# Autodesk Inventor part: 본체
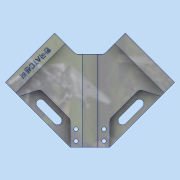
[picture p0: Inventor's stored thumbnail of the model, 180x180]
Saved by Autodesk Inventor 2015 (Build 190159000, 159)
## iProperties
Created: 2019-04
Part Number: 본체
Material: 알루미늄 6061
Document SubType Name: Modeling
Designer: SCD-A02
Density: 2.7 g/cm^3
Appearance: 알루미늄 - 평지
Mass: 601.509 g
Surface Area: 426.536 cm^2
Volume: 222.781 cm^3
Author: SCD-A02
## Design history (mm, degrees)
sketch "스케치1"
  geometry: L1 (-84.853, 0)-(0, 84.853); L2 (0, 84.853)-(84.853, 0); L3 (84.853, 0)-(0, -84.853); L4 (0, -84.853)-(-84.853, 0); L5 (-84.853, 0)-(84.853, 0); L6 (0, 84.853)-(0, -84.853); 1 further point
  constraints: 12 end point, 2 midpoint, 2 parallel, 1 perpendicular
extrude "돌출1" new body sketch "스케치1" distance "d2" = 18; taper "d3" = 0 deg
sketch "스케치2"
  geometry: L1 (0, 84.853)-(-84.853, 0) reference; L2 (-84.853, 0)-(0, -84.853) reference; L3 (0, -84.853)-(84.853, 0) reference; L4 (84.853, 0)-(0, 84.853) reference; L5 (-84.853, 0)-(-50.467, -34.386); L6 (-84.853, 0)-(-49.497, 35.355); L7 (64.853, 0)-(64.853, 20); L8 (64.853, 0)-(64.853, -20); L9 (64.853, -20)-(84.853, 0); L10 (84.853, 0)-(64.853, 20); 1 further point
  constraints: 12 end point, 5 point on line, 1 collinear, 1 vertical
  dimensions: "d6" = 20 distance of L3.end L7.start; "d7" = 20 distance from line of L3.end L8; "d8" = 70 distance from line of L6.end L4; "d9" = 48.62899 distance from line of L5.end L1
extrude "돌출2" cut sketch "스케치2" distance "d10" = 18; taper "d11" = 0 deg
sketch "스케치3"
  geometry: L1 (64.853, -20)-(64.853, 20) reference; L2 (64.853, 20)-(0, 84.853) reference; L3 (0, -84.853)-(64.853, -20) reference; L4 (64.853, 0)-(-28.147, 0); L5 (-84.853, 0)-(-49.497, -35.355); L6 (-84.853, 0)-(-49.497, 35.355); L7 (-49.497, -35.355)-(-28.147, -14.005); L8 (-49.497, 35.355)-(-28.147, 14.005); L9 (-28.147, 0)-(-28.147, 5.408); L10 (-28.147, 5.408)-(-28.147, 14.005); L11 (-28.147, 0)-(-28.147, -14.005); 1 further point
  constraints: 16 end point, 5 parallel, 1 horizontal, 1 midpoint, 1 point on line, 1 vertical
  dimensions: "d12" = 93 distance of L4.start L4.end; "d13" = 50 distance of L5.start L5.end; "d14" = 50 distance of L5.start L6.end; "d15" = 76.07918 distance from line of L9.end L2
extrude "돌출3" cut sketch "스케치3" stored distance "d16" = 0; taper "d17" = 0 deg
sketch "스케치4"
  geometry: L1 (-28.147, 14.005)-(-28.147, -14.005) reference; L2 (64.853, -20)-(64.853, 20) reference; L3 (-28.147, 0)-(64.853, 0); L4 (-28.147, -8)-(64.853, -8); L5 (-28.147, 8)-(64.853, 8); L6 (-28.147, -8)-(-28.147, 8); L7 (64.853, -8)-(64.853, 8); 1 further point
  constraints: 10 end point, 2 midpoint, 2 parallel, 1 collinear, 1 perpendicular, 1 point on line
  dimensions: "d18" = 8 distance between parallel lines of L3 L4; "d19" = 8 distance between parallel lines of L3 L5
extrude "돌출4" cut sketch "스케치4" distance "d20" = 3.5; taper "d21" = 0 deg
sketch "스케치5"
  geometry: L1 (-64.853, 20)-(-64.853, -20) reference; L2 (28.147, -14.005)-(28.147, 14.005) reference; L3 (-64.853, 8)-(-64.853, -8) reference; L4 (28.147, 8)-(-64.853, 8) reference; L5 (28.147, -8)-(28.147, 8) reference; L6 (-64.853, -8)-(28.147, -8) reference; L7 (-64.853, 0)-(28.147, 0); L8 (-64.853, 6)-(28.147, 6); L9 (-64.853, -6)-(28.147, -6); L10 (-64.853, -6)-(-64.853, 6); L11 (28.147, -6)-(28.147, 6); 1 further point
  constraints: 10 end point, 2 collinear, 2 midpoint, 2 parallel
  dimensions: "d22" = 6 distance between parallel lines of L7 L8; "d23" = 6 distance between parallel lines of L7 L9
extrude "돌출5" cut sketch "스케치5" distance "d24" = 3; taper "d25" = 0 deg
sketch "스케치6"
  geometry: L1 (-49.497, -35.355)-(0, -84.853) reference; L2 (0, -84.853)-(64.853, -20) reference; L3 (-28.147, -14.005)-(-28.147, -8) reference; L4 (-28.147, -8)-(64.853, -8) reference; L5 (64.853, -8)-(64.853, -20) reference; L6 (64.853, -20)-(0, -84.853) reference; L7 (0, -84.853)-(-49.497, -35.355) reference; L8 (-49.497, -35.355)-(-28.147, -14.005) reference; L9 (-28.147, 8)-(-28.147, 14.005) reference; L10 (-28.147, 14.005)-(-49.497, 35.355) reference; L11 (-49.497, 35.355)-(0, 84.853) reference; L12 (0, 84.853)-(64.853, 20) reference; L13 (64.853, 20)-(64.853, 8) reference; L14 (64.853, 8)-(-28.147, 8) reference; L15 (-38.891, -24.749)-(10.607, -74.246); L16 (0, -84.853)-(10.607, -74.246); L17 (-49.497, -35.355)-(-38.891, -24.749); 1 further point
  constraints: 6 end point, 2 collinear, 1 parallel
  dimensions: "d26" = 15 distance between parallel lines of L1 L15
extrude "돌출6" join sketch "스케치6" distance "d27" = 24; taper "d28" = 0 deg
sketch "스케치7"
  geometry: L1 (0, 84.853)-(-49.497, 35.355) reference; L2 (-28.147, -14.005)-(-28.147, -8) reference; L3 (-28.147, -8)-(64.853, -8) reference; L4 (64.853, -8)-(64.853, -20) reference; L5 (64.853, -20)-(10.607, -74.246) reference; L6 (-38.891, -24.749)-(10.607, -74.246) reference; L7 (-49.497, -35.355)-(-38.891, -24.749) reference; L8 (0, -84.853)-(-49.497, -35.355) reference; L9 (10.607, -74.246)-(0, -84.853) reference; L10 (-38.891, -24.749)-(-28.147, -14.005) reference; L11 (-28.147, 8)-(-28.147, 14.005) reference; L12 (-28.147, 14.005)-(-49.497, 35.355) reference; L13 (-49.497, 35.355)-(0, 84.853) reference; L14 (0, 84.853)-(64.853, 20) reference; L15 (64.853, 20)-(64.853, 8) reference; L16 (64.853, 8)-(-28.147, 8) reference; L17 (10.607, 74.246)-(-38.891, 24.749); L18 (-38.891, 24.749)-(-49.497, 35.355); L19 (10.607, 74.246)-(0, 84.853); 1 further point
  constraints: 6 end point, 2 collinear, 1 parallel
  dimensions: "d29" = 15 distance between parallel lines of L1 L17
extrude "돌출7" join sketch "스케치7" distance "d30" = 24; taper "d31" = 0 deg
sketch "스케치8"
  geometry: L1 (10.607, -74.246)-(64.853, -20) reference; L2 (-28.147, -14.005)-(-28.147, -8) reference; L3 (-28.147, -8)-(64.853, -8) reference; L4 (64.853, -8)-(64.853, -20) reference; L5 (64.853, -20)-(10.607, -74.246) reference; L6 (-38.891, -24.749)-(10.607, -74.246) reference; L7 (-49.497, -35.355)-(-38.891, -24.749) reference; L8 (0, -84.853)-(-49.497, -35.355) reference; L9 (10.607, -74.246)-(0, -84.853) reference; L10 (-38.891, -24.749)-(-28.147, -14.005) reference; L11 (-28.147, 8)-(-28.147, 14.005) reference; L12 (-28.147, 14.005)-(-38.891, 24.749) reference; L13 (10.607, 74.246)-(-38.891, 24.749) reference; L14 (0, 84.853)-(10.607, 74.246) reference; L15 (-49.497, 35.355)-(0, 84.853) reference; L16 (-38.891, 24.749)-(-49.497, 35.355) reference; L17 (64.853, 8)-(-28.147, 8) reference; L18 (64.853, 20)-(64.853, 8) reference; L19 (10.607, 74.246)-(64.853, 20) reference; L20 (-28.147, -14.005)-(-28.147, -8) reference; L21 (-28.147, -8)-(64.853, -8) reference; L22 (64.853, -8)-(64.853, -20) reference; L23 (64.853, -20)-(10.607, -74.246) reference; L24 (-38.891, -24.749)-(10.607, -74.246) reference; L25 (-49.497, -35.355)-(-38.891, -24.749) reference; L26 (0, -84.853)-(-49.497, -35.355) reference; L27 (10.607, -74.246)-(0, -84.853) reference; L28 (-38.891, -24.749)-(-28.147, -14.005) reference; L29 (-28.147, 8)-(-28.147, 14.005) reference; L30 (-28.147, 14.005)-(-38.891, 24.749) reference; L31 (10.607, 74.246)-(-38.891, 24.749) reference; L32 (0, 84.853)-(10.607, 74.246) reference; L33 (-49.497, 35.355)-(0, 84.853) reference; L34 (-38.891, 24.749)-(-49.497, 35.355) reference; L35 (64.853, 8)-(-28.147, 8) reference; L36 (64.853, 20)-(64.853, 8) reference; L37 (10.607, 74.246)-(64.853, 20) reference; L38 (-28.147, -14.005)-(-28.147, -8) reference; L39 (-28.147, -8)-(64.853, -8) reference; L40 (64.853, -8)-(64.853, -20) reference; L41 (64.853, -20)-(10.607, -74.246) reference; L42 (-38.891, -24.749)-(10.607, -74.246) reference; L43 (-49.497, -35.355)-(-38.891, -24.749) reference; L44 (0, -84.853)-(-49.497, -35.355) reference; L45 (10.607, -74.246)-(0, -84.853) reference; L46 (-38.891, -24.749)-(-28.147, -14.005) reference; L47 (-28.147, 8)-(-28.147, 14.005) reference; L48 (-28.147, 14.005)-(-38.891, 24.749) reference; L49 (10.607, 74.246)-(-38.891, 24.749) reference; L50 (0, 84.853)-(10.607, 74.246) reference; L51 (-49.497, 35.355)-(0, 84.853) reference; L52 (-38.891, 24.749)-(-49.497, 35.355) reference; L53 (64.853, 8)-(-28.147, 8) reference; L54 (64.853, 20)-(64.853, 8) reference; L55 (10.607, 74.246)-(64.853, 20) reference; L56 (64.853, 0)-(23.588, 0); L57 (64.853, -20)-(36.569, -20); L58 (14.142, -70.711)-(7.071, -49.497); L59 (-28.147, -14.005)-(-28.147, -8) reference; L60 (-28.147, -8)-(64.853, -8) reference; L61 (64.853, -8)-(64.853, -20) reference; L62 (64.853, -20)-(10.607, -74.246) reference; L63 (-38.891, -24.749)-(10.607, -74.246) reference; L64 (-49.497, -35.355)-(-38.891, -24.749) reference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; 1 further point
  constraints: 14 end point, 3 parallel, 3 point on line, 1 collinear, 1 horizontal
  dimensions: "d35" = 20 distance between parallel lines of L56 L57; "d57" = 18.4349 deg angle of L18 L58; "d58" = 8 distance between parallel lines of L17 L56; "d59" = 20 distance between parallel lines of L5 L77; "d60" = 80 distance between parallel lines of L14 L78; "d61" = 76.79361 distance from line of L18.start L58; "d62" = 14.14214 distance from line of L56.start L79; "d63" = 43.32107 distance from line of L56.end L79; "d64" = 100 distance from line of L58.start L79; "d65" = 86.06602 distance from line of L78.start L36
extrude "돌출10" cut sketch "스케치8" distance "d68" = 10; taper "d69" = 0 deg
sketch "스케치9"
  geometry: L1 (64.853, -20)-(14.142, -70.711) reference; L2 (-28.147, -14.005)-(-28.147, 14.005) reference; L3 (-28.147, 14.005)-(-49.497, 35.355) reference; L4 (-49.497, 35.355)-(0, 84.853) reference; L5 (0, 84.853)-(64.853, 20) reference; L6 (64.853, 20)-(64.853, -20) reference; L7 (64.853, -20)-(14.142, -70.711) reference; L8 (14.142, -70.711)-(0, -84.853) reference; L9 (0, -84.853)-(-49.497, -35.355) reference; L10 (-49.497, -35.355)-(-28.147, -14.005) reference; L11 (64.853, -20)-(36.569, -20) reference; L12 (36.569, -20)-(7.071, -49.497) reference; L13 (7.071, -49.497)-(14.142, -70.711) reference; L14 (24.395, -52.679)-(41.366, -35.709); L15 (18.031, -46.315)-(35.002, -29.345); A1 r 4.5 centre (21.213, -49.497) between (18.031, -46.315) and (24.395, -52.679); A2 r 4.5 centre (38.184, -32.527) between (41.366, -35.709) and (35.002, -29.345); 1 further point
  constraints: 4 end point, 4 point on circle, 4 tangent, 2 centre point, 2 parallel
  dimensions: "d75" = 4.5 radius of A2; "d76" = 5.5 distance between parallel lines of L1 L14; "d77" = 23.48707 distance from line of L14.end L6; "d78" = 40.45763 distance from line of L14.start L6
extrude "돌출11" cut sketch "스케치9" stored distance "d79" = 10; taper "d80" = 0 deg
sketch "스케치10"
  geometry: L1 (64.853, -20)-(64.853, -8) reference; L2 (64.853, 0)-(27.579, 0); L3 (64.853, -14)-(27.579, -14); L4 (-28.147, -14.005)-(-28.147, -8) reference; L5 (-28.147, -8)-(64.853, -8) reference; L6 (64.853, -8)-(64.853, -20) reference; L7 (64.853, -20)-(36.569, -20) reference; L8 (36.569, -20)-(7.071, -49.497) reference; L9 (7.071, -49.497)-(14.142, -70.711) reference; L10 (14.142, -70.711)-(10.607, -74.246) reference; L11 (10.607, -74.246)-(0, -84.853) reference; L12 (0, -84.853)-(-49.497, -35.355) reference; L13 (-49.497, -35.355)-(-38.891, -24.749) reference; L14 (-38.891, -24.749)-(-28.147, -14.005) reference; L15 (-38.891, -24.749)-(10.607, -74.246) reference; L16 (-28.147, 8)-(-28.147, 14.005) reference; L17 (-28.147, 14.005)-(-38.891, 24.749) reference; L18 (10.607, 74.246)-(-38.891, 24.749) reference; L19 (0, 84.853)-(10.607, 74.246) reference; L20 (-49.497, 35.355)-(0, 84.853) reference; L21 (-38.891, 24.749)-(-49.497, 35.355) reference; L22 (64.853, 8)-(-28.147, 8) reference; L23 (64.853, 20)-(64.853, 8) reference; L24 (10.607, 74.246)-(64.853, 20) reference; L25 (58.853, -20)-(58.853, -8); L26 (46.853, -20)-(46.853, -8); 3 further points
  constraints: 8 end point, 3 parallel, 2 midpoint, 1 horizontal
  dimensions: "d81" = 14 distance between parallel lines of L2 L3; "d82" = 6 distance between parallel lines of L1 L25; "d83" = 12 distance between parallel lines of L25 L26
hole "구멍1" sketch "스케치10" at (46.853, -14), (58.853, -14) diameter "d84" = 4.5; stored, may be unused: countersink angle "d88" = 90 deg, drill point angle "d90" = 0 deg; dims "d85" = 6, "d86" = 4, "d87" = 2, "d89" = 8
sketch "스케치11"
  geometry: L1 (-18.031, -46.315)-(-35.002, -29.345) reference; L2 (-41.366, -35.709)-(-24.395, -52.679) reference; L3 (-64.853, -6)-(28.147, -6) reference; L4 (28.147, -6)-(28.147, -14.005) reference; L5 (28.147, -14.005)-(49.497, -35.355) reference; L6 (49.497, -35.355)-(0, -84.853) reference; L7 (0, -84.853)-(-64.853, -20) reference; L8 (-64.853, -20)-(-64.853, -6) reference; L9 (28.147, 6)-(-64.853, 6) reference; L10 (-64.853, 6)-(-64.853, 20) reference; L11 (-64.853, 20)-(0, 84.853) reference; L12 (0, 84.853)-(49.497, 35.355) reference; L13 (49.497, 35.355)-(28.147, 14.005) reference; L14 (28.147, 14.005)-(28.147, 6) reference; C1 r 2.25 at (-46.853, -14) reference; C2 r 2.25 at (-46.853, -14) reference; C3 r 2.25 at (-46.853, -14) reference; C4 r 2.25 at (-58.853, -14) reference; C5 r 2.25 at (-58.853, -14) reference; A1 r 4.5 centre (-38.184, -32.527) between (-35.002, -29.345) and (-41.366, -35.709) reference; A2 r 4.5 centre (-21.213, -49.497) between (-24.395, -52.679) and (-18.031, -46.315) reference; 3 further points
  constraints: 2 coincident
hole "구멍2" sketch "스케치11" at (-58.853, -14), (-46.853, -14) diameter "d91" = 8; stored, may be unused: countersink angle "d95" = 90 deg, drill point angle "d97" = 0 deg; dims "d92" = 6, "d93" = 4, "d94" = 2, "d96" = 10
fillet "모깎기1" dims "d98" = 5
fillet "모깎기3" dims "d100" = 5
fillet "모깎기4" dims "d101" = 5
sketch "스케치12"
  geometry: L1 (-49.497, -35.355)-(0, -84.853) reference; L2 (-38.891, -24.749)-(-49.497, -35.355) reference; 2 further points
  constraints: 1 other
  dimensions: "d102" = 35 distance from line of point (-19.445, -54.801) L2; "d103" = 7.5 distance from line of L1 point (-19.445, -54.801)
feature "엠보싱1" sketch "스케치12" dims "d104" = 0.5, "d105" = 0
node "솔리드1"
mirror "대칭1"
node "투영된 루프1"
node "투영된 루프2"
node "투영된 루프3"
node "절단 모서리 투영1"
node "절단 모서리 투영2"
node "절단 모서리 투영3"
node "절단 모서리 투영4"
node "절단 모서리 투영5"
node "절단 모서리 투영6"
node "절단 모서리 투영7"
node "절단 모서리 투영8"
node "절단 모서리 투영9"
